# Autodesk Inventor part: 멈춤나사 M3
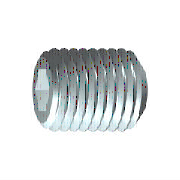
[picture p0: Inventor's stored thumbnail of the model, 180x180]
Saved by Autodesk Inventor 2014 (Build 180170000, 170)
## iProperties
IsCustomPart: 1
Created: 2012-02
Part Number: 멈춤나사 M3
Material: 강철, 연강
Description: 6각 소켓 머리 없는 멈춤 나사
Document SubType Name: Modeling
Standard: KS B 1028
Designer: mduedu
Standards Organization: KS
Language: ko-KR
Size Designation: 납작점M3x8
Categories: <MemberInstance><Categories><Category DisplayName="조임쇠" InternalName="e4da775c-781d-43d5-af7c-5136215cf5a6" Mnemonic="FSTN"><Category DisplayName="볼트" InternalN
Density: 1 g/cm^3
Appearance: 강철
Author: mduedu
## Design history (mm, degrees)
sketch "스케치1"
  geometry: L1 (0, 0)-(5.5, 0); L2 (8, 0.866)-(8, 1.5); L3 (8, 1.5)-(0, 1.5); L4 (8, 0.866)-(6, 0.866); L5 (6, 0.866)-(5.5, 0); L6 (0, -0.3)-(0, 1.8) reference; L7 (0, 1.5)-(0, 0)
  constraints: 13 end point, 3 parallel, 1 collinear, 1 perpendicular, 1 point on line
  dimensions: "d0" = 2 distance of L2.start L4.end (= INTI); "d1" = 60 deg angle of L5 L1; "d2" = 3 diameter of L3 L1 (= NND); "d3" = 1.73205 diameter of L4 L1 (= 1.1547 x SW); "d5" = 8 distance from line of L2 L3.end (= NLG)
revolve "본체" sketch "스케치1" stored, may be unused: angle "d6" = 90 deg
sketch "스케치2"
  geometry: L1 (-0.433, 0.75)-(0.433, 0.75); L2 (0.433, 0.75)-(0.866, 0); L3 (0.866, 0)-(0.433, -0.75); L4 (0.433, -0.75)-(-0.433, -0.75); L5 (-0.433, -0.75)-(-0.866, 0); L6 (-0.866, 0)-(-0.433, 0.75); A1 r 0.866 centre (0, 0) between (-0.433, 0.75) and (0.433, 0.75) reference; 2 further points
  constraints: 12 end point, 2 point on circle, 1 coincident, 1 horizontal, 11 other
extrude "슬롯" join sketch "스케치2" taper "d9" = 0 deg; stored distance "d21" = 10
workaxis "Work Axis1"
workplane "Work Plane1"
body "Solid1"
chamfer "모따기1" distance "d7" = 0.30673 (= -0.5 x GD1 + 0.5 x NND); stored, may be unused: angle "d8" = 45 deg (= FAWI), second distance "d29" = 0.30673 (= -0.5 x GD1 + 0.5 x NND)
feature "스레드" dims "d11" = 8 (= NLG), "d12" = 0
chamfer "모따기2" distance "d13" = 0.30673 (= -0.5 x GD1 + 0.5 x NND); stored, may be unused: angle "d14" = 45 deg (= FAWI), second distance "d30" = 0.30673 (= -0.5 x GD1 + 0.5 x NND)
other parameters: "NND" = 3 [user parameter; used in 5 equation terms], "NLG" = 8 [user parameter; used in 2 equation terms], "INTI" = 2 [user parameter; used in 1 equation term], "FAWI" = 45 deg [user parameter; used in 2 equation terms], "SW" = 1.5 [user parameter; used in 2 equation terms], "GD1" = 2.38655 (= THREADDIA - 1.2269 x PTC) [user parameter; used in 4 equation terms], "d4" = 0, "FAWI1" = 45 deg [user parameter], "d15" = 0, "d31" = 0, "GUL" = 0.30673 (= 0.61345 x PTC) [user parameter], "SPD" = 2 [user parameter], "TOA" = 30 deg [user parameter], "THREADDIA" = 3 [user parameter; used in 1 equation term], "PTC" = 0.5 [user parameter; used in 4 equation terms], "GAL" = 0.30673 (= 0.61345 x PTC) [user parameter], "E0" = 1.7325 (= 1.155 x SW) [user parameter]
